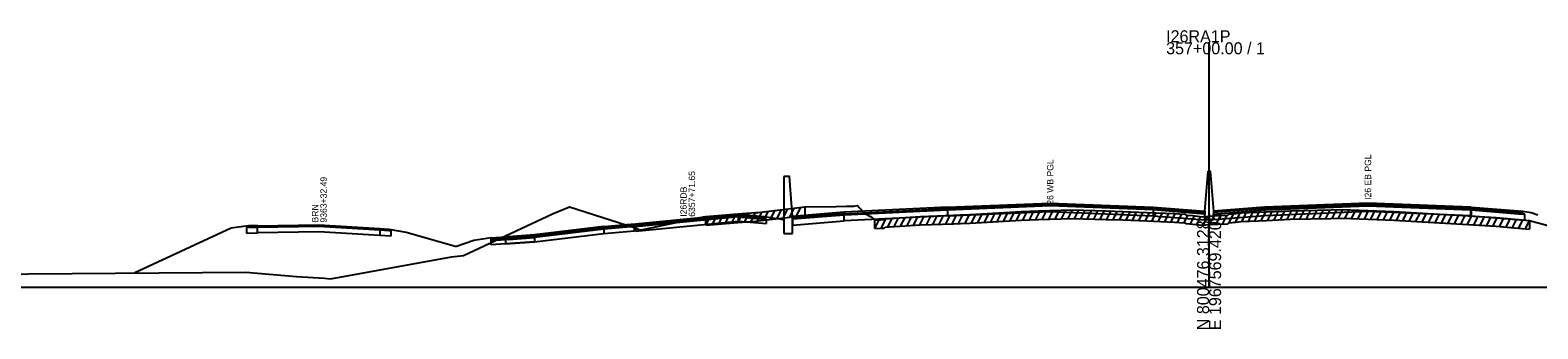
# Model space of a CAD drawing. Extents: x 1017 to 19997, y -1947 to 50737.
# Drawn here: x 14325.4 to 14676.6, y 6990.3 to 7060 of the extents above; entities that cross this region are included whole.
import ezdxf

# ---------------------------------------------------------------- set-up
doc = ezdxf.new("R2010")
doc.units = 0
for name, color, linetype in [('RD_GPK_XS_Cell', 7, 'Continuous'), ('RD_XS_Base', 7, 'Continuous'), ('RD_XS_ExGround', 7, 'Continuous'), ('RD_XS_ExPaveRet', 7, 'Continuous'), ('RD_XS_Greenside', 7, 'Continuous'), ('RD_XS_MedBWall', 7, 'Continuous'), ('RD_XS_Pave', 7, 'Continuous'), ('RD_XS_PaveOvlay', 7, 'Continuous'), ('RD_XS_TX_Notes', 7, 'Continuous')]:
    doc.layers.add(name, color=color, linetype=linetype)

msp = doc.modelspace()

# ---------------------------------------------------------------- linework, layer by layer
at = {"layer": 'RD_GPK_XS_Cell'}
for p, q in [((14600, 7000), (14600, 7057.14)), ((14000, 7000), (14600, 7000)), ((14600, 7000), (15200, 7000))]:
    msp.add_line(p, q, dxfattribs=at)
at = {"layer": 'RD_XS_Base'}
for points in [[(14490.4, 7015.41), (14490.4, 7016.41)], [(14496.9, 7015.88), (14496.4, 7015.92), (14490.4, 7016.41)], [(14496.9, 7014.88), (14496.9, 7015.88)], [(14515, 7016.82), (14503, 7015.86)], [(14503, 7015.86), (14503, 7014.52)], [(14515, 7015.48), (14515, 7016.82)], [(14539.05, 7016.68), (14515, 7015.48)], [(14539.05, 7018.02), (14539.05, 7016.68)], [(14539.05, 7016.68), (14563, 7017.65), (14587, 7016.69)], [(14599, 7017.08), (14587, 7018.03)], [(14587, 7018.03), (14587, 7016.69)], [(14587, 7016.69), (14599, 7015.74)], [(14599, 7015.74), (14599, 7017.08)], [(14601, 7015.74), (14601, 7017.08)], [(14613, 7016.69), (14601, 7015.74)], [(14613, 7016.69), (14613, 7018.03)], [(14660.95, 7016.69), (14637, 7017.65), (14613, 7016.69)], [(14660.95, 7016.69), (14660.95, 7018.03)], [(14661, 7016.69), (14660.95, 7016.69)], [(14661, 7018.03), (14661, 7016.69)], [(14673.5, 7017.03), (14673, 7017.07), (14661, 7018.03)], [(14661, 7016.69), (14673.5, 7015.69)], [(14673.5, 7015.69), (14673.5, 7017.03)], [(14378.35, 7014.02), (14375.8, 7013.98)], [(14375.8, 7013.98), (14375.8, 7012.65)], [(14375.8, 7012.65), (14378.35, 7012.69)], [(14378.35, 7014.02), (14392.63, 7014.26), (14406.9, 7013.39)], [(14378.35, 7012.69), (14378.35, 7014.02)], [(14406.9, 7012.08), (14392.63, 7012.93), (14378.35, 7012.69)], [(14406.9, 7013.39), (14406.9, 7012.08)], [(14406.9, 7013.39), (14408.94, 7013.27), (14409.45, 7013.24)], [(14409.45, 7011.9), (14406.9, 7012.08)], [(14409.45, 7013.24), (14409.45, 7011.9)], [(14442.9, 7010.6), (14459.08, 7012.56)], [(14466.17, 7014.17), (14459.08, 7013.56)], [(14459.08, 7013.56), (14459.08, 7012.56)], [(14459.08, 7012.56), (14466.17, 7013.17)], [(14466.17, 7013.17), (14466.17, 7014.17)], [(14466.4, 7013.11), (14478.4, 7014.26), (14490.4, 7015.41)], [(14466.4, 7014.11), (14466.4, 7013.11)], [(14490.4, 7015.41), (14496.9, 7014.88)], [(14503, 7014.52), (14515, 7015.48)], [(14432.79, 7010.9), (14442.9, 7011.6)], [(14432.79, 7009.9), (14432.79, 7010.9)], [(14442.9, 7010.6), (14432.79, 7009.9)], [(14442.9, 7011.6), (14436.84, 7011.18), (14436.13, 7011.13)], [(14436.13, 7011.13), (14436.13, 7010.13)], [(14436.13, 7010.13), (14442.9, 7010.6)], [(14442.9, 7011.6), (14442.9, 7010.6)]]:
    msp.add_lwpolyline(points, dxfattribs=at)
at = {"layer": 'RD_XS_ExGround'}
msp.add_lwpolyline([(14314.9, 7003.09), (14375.7, 7003.54), (14387.45, 7002.53), (14393.97, 7002.1), (14395.27, 7002.01), (14397.59, 7002.39), (14423.56, 7007.1), (14426.37, 7007.42), (14447.06, 7017.15), (14451.01, 7018.79), (14466.33, 7013.86), (14467.41, 7013.37), (14468.14, 7013.51), (14482.23, 7016.43), (14482.83, 7016.53), (14490.26, 7017.11), (14494.41, 7017.43), (14494.96, 7017.48), (14495.64, 7017.56), (14505.85, 7018.73), (14513.19, 7018.84), (14515.51, 7018.92), (14517.24, 7018.94), (14518.12, 7019.05), (14518.53, 7018.65), (14519.74, 7017.32), (14520.17, 7017.03), (14521.13, 7016.51), (14522.16, 7015.71), (14523.47, 7015.76), (14524.34, 7015.82), (14524.6, 7016.02), (14525.57, 7016.08), (14532.83, 7016.55), (14540.45, 7016.82), (14542.11, 7016.88), (14544.31, 7016.95), (14545.68, 7017.03), (14556.22, 7017.67), (14560.31, 7017.8), (14568.2, 7018.06), (14575.99, 7017.83), (14579.9, 7017.71), (14585.48, 7017.47), (14591.92, 7017.21), (14593.13, 7017.13), (14594.37, 7017.02), (14594.7, 7016.86), (14596.22, 7016.72), (14598.39, 7016.46), (14600.12, 7016.62), (14601.02, 7016.69), (14602.13, 7016.73), (14604.37, 7016.79), (14604.63, 7017.03), (14606.23, 7017.21), (14607.45, 7017.36), (14613.4, 7017.62), (14618.97, 7017.87), (14628.39, 7018.06), (14631.11, 7018.13), (14634.94, 7017.97), (14643.14, 7017.68), (14653.64, 7017.06), (14655.09, 7016.98), (14666.83, 7016.28), (14668.54, 7016.12), (14674.62, 7015.56), (14687.54, 7012.1)], dxfattribs=at)
at = {"layer": 'RD_XS_ExPaveRet'}
for p, q in [((14482.83, 7014.53), (14483.87, 7016.61)), ((14482.83, 7014.53), (14482.83, 7016.53)), ((14484.33, 7014.65), (14485.37, 7016.73)), ((14485.83, 7014.77), (14486.87, 7016.85)), ((14487.33, 7014.88), (14488.37, 7016.96)), ((14488.83, 7015), (14489.87, 7017.08)), ((14490.33, 7015.11), (14491.37, 7017.19)), ((14491.83, 7015.23), (14492.87, 7017.31)), ((14493.33, 7015.35), (14494.37, 7017.43)), ((14494.83, 7015.47), (14495.89, 7017.59)), ((14495.64, 7015.56), (14505.85, 7016.73)), ((14496.33, 7015.64), (14497.39, 7017.76)), ((14497.83, 7015.81), (14498.89, 7017.93)), ((14499.33, 7015.98), (14500.39, 7018.1)), ((14500.83, 7016.15), (14501.89, 7018.28)), ((14502.33, 7016.33), (14503.39, 7018.45)), ((14503.83, 7016.5), (14504.89, 7018.62)), ((14505.85, 7018.73), (14505.85, 7016.73)), ((14522.16, 7013.71), (14523.17, 7015.75)), ((14522.16, 7013.71), (14522.16, 7015.71)), ((14523.66, 7013.77), (14524.79, 7016.03)), ((14525.16, 7014.06), (14526.19, 7016.12)), ((14526.66, 7014.15), (14527.69, 7016.22)), ((14528.16, 7014.25), (14529.19, 7016.31)), ((14529.66, 7014.34), (14530.69, 7016.41)), ((14531.16, 7014.44), (14532.19, 7016.51)), ((14532.66, 7014.54), (14533.68, 7016.58)), ((14534.16, 7014.59), (14535.17, 7016.63)), ((14535.66, 7014.65), (14536.67, 7016.68)), ((14537.16, 7014.7), (14538.17, 7016.74)), ((14538.66, 7014.76), (14539.67, 7016.79)), ((14540.16, 7014.81), (14541.17, 7016.84)), ((14541.66, 7014.86), (14542.67, 7016.9)), ((14543.16, 7014.91), (14544.17, 7016.95)), ((14544.66, 7014.97), (14545.69, 7017.03)), ((14545.68, 7015.03), (14556.22, 7015.67)), ((14546.16, 7015.06), (14547.19, 7017.12)), ((14547.66, 7015.15), (14548.69, 7017.21)), ((14549.16, 7015.24), (14550.19, 7017.3)), ((14550.66, 7015.33), (14551.69, 7017.39)), ((14552.16, 7015.42), (14553.19, 7017.49)), ((14553.66, 7015.51), (14554.69, 7017.58)), ((14555.16, 7015.6), (14556.19, 7017.67)), ((14556.22, 7015.67), (14560.31, 7015.8)), ((14556.66, 7015.68), (14557.67, 7017.71)), ((14558.16, 7015.73), (14559.17, 7017.76)), ((14559.66, 7015.78), (14560.67, 7017.81)), ((14560.31, 7015.8), (14568.2, 7016.06)), ((14561.16, 7015.83), (14562.17, 7017.86)), ((14562.66, 7015.88), (14563.67, 7017.91)), ((14564.16, 7015.93), (14565.17, 7017.96)), ((14565.66, 7015.98), (14566.67, 7018.01)), ((14567.16, 7016.03), (14568.17, 7018.06)), ((14568.2, 7016.06), (14575.99, 7015.83)), ((14568.66, 7016.05), (14569.64, 7018.02)), ((14570.16, 7016), (14571.14, 7017.97)), ((14571.66, 7015.96), (14572.64, 7017.93)), ((14573.16, 7015.91), (14574.14, 7017.88)), ((14574.66, 7015.87), (14575.64, 7017.84)), ((14575.99, 7015.83), (14579.9, 7015.71)), ((14576.16, 7015.82), (14577.14, 7017.79)), ((14577.66, 7015.78), (14578.64, 7017.75)), ((14579.16, 7015.73), (14580.14, 7017.7)), ((14579.9, 7015.71), (14585.48, 7015.47)), ((14580.66, 7015.68), (14581.63, 7017.64)), ((14582.16, 7015.61), (14583.13, 7017.57)), ((14583.66, 7015.55), (14584.63, 7017.51)), ((14585.16, 7015.49), (14586.14, 7017.45)), ((14586.66, 7015.43), (14587.64, 7017.39)), ((14588.16, 7015.37), (14589.14, 7017.33)), ((14589.66, 7015.3), (14590.64, 7017.26)), ((14591.16, 7015.24), (14592.13, 7017.2)), ((14592.66, 7015.16), (14593.62, 7017.09)), ((14594.16, 7015.04), (14595.05, 7016.83)), ((14595.66, 7014.77), (14596.61, 7016.67)), ((14597.16, 7014.61), (14598.1, 7016.49)), ((14598.66, 7014.48), (14599.7, 7016.58)), ((14600.16, 7014.62), (14601.19, 7016.7)), ((14601.66, 7014.71), (14602.67, 7016.74)), ((14603.16, 7014.76), (14604.17, 7016.78)), ((14604.66, 7015.03), (14605.71, 7017.15)), ((14606.16, 7015.2), (14607.22, 7017.33)), ((14607.45, 7015.36), (14613.4, 7015.62)), ((14607.66, 7015.37), (14608.68, 7017.41)), ((14609.16, 7015.43), (14610.18, 7017.48)), ((14610.66, 7015.5), (14611.68, 7017.54)), ((14612.16, 7015.56), (14613.18, 7017.61)), ((14613.4, 7015.62), (14618.97, 7015.87)), ((14613.66, 7015.63), (14614.68, 7017.67)), ((14615.16, 7015.7), (14616.18, 7017.74)), ((14616.66, 7015.76), (14617.68, 7017.81)), ((14618.16, 7015.83), (14619.18, 7017.87)), ((14618.97, 7015.87), (14628.39, 7016.06)), ((14619.66, 7015.88), (14620.67, 7017.9)), ((14621.16, 7015.91), (14622.17, 7017.93)), ((14622.66, 7015.94), (14623.67, 7017.97)), ((14624.16, 7015.98), (14625.17, 7018)), ((14625.66, 7016.01), (14626.67, 7018.03)), ((14627.16, 7016.04), (14628.17, 7018.06)), ((14628.39, 7016.06), (14631.11, 7016.13)), ((14628.66, 7016.07), (14629.67, 7018.09)), ((14630.16, 7016.1), (14631.17, 7018.12)), ((14631.11, 7016.13), (14634.94, 7015.97)), ((14631.66, 7016.1), (14632.64, 7018.06)), ((14633.16, 7016.04), (14634.14, 7018)), ((14634.66, 7015.98), (14635.64, 7017.95)), ((14634.94, 7015.97), (14643.14, 7015.68)), ((14636.16, 7015.93), (14637.14, 7017.89)), ((14637.66, 7015.87), (14638.64, 7017.84)), ((14639.16, 7015.82), (14640.14, 7017.79)), ((14640.66, 7015.77), (14641.64, 7017.73)), ((14642.16, 7015.72), (14643.14, 7017.68)), ((14643.14, 7015.68), (14653.64, 7015.06)), ((14643.66, 7015.65), (14644.63, 7017.59)), ((14645.16, 7015.56), (14646.13, 7017.51)), ((14646.66, 7015.47), (14647.63, 7017.42)), ((14648.16, 7015.39), (14649.13, 7017.33)), ((14649.66, 7015.3), (14650.63, 7017.24)), ((14651.16, 7015.21), (14652.13, 7017.15)), ((14652.66, 7015.12), (14653.63, 7017.06)), ((14654.16, 7015.03), (14655.13, 7016.97)), ((14655.66, 7014.94), (14656.63, 7016.89)), ((14657.16, 7014.85), (14658.13, 7016.8)), ((14658.66, 7014.76), (14659.63, 7016.71)), ((14660.16, 7014.68), (14661.13, 7016.62)), ((14661.66, 7014.59), (14662.63, 7016.53)), ((14663.16, 7014.5), (14664.13, 7016.44)), ((14664.66, 7014.41), (14665.63, 7016.35)), ((14666.16, 7014.32), (14667.12, 7016.25)), ((14667.66, 7014.2), (14668.61, 7016.11)), ((14669.16, 7014.06), (14670.11, 7015.98)), ((14670.66, 7013.93), (14671.61, 7015.84)), ((14672.16, 7013.79), (14673.11, 7015.7)), ((14482.83, 7014.53), (14490.26, 7015.11)), ((14490.26, 7015.11), (14494.41, 7015.43)), ((14494.41, 7015.43), (14494.96, 7015.48)), ((14494.96, 7015.48), (14495.64, 7015.56)), ((14522.16, 7013.71), (14523.47, 7013.76)), ((14523.47, 7013.76), (14524.34, 7013.82)), ((14524.34, 7013.82), (14524.6, 7014.02)), ((14524.6, 7014.02), (14525.57, 7014.08)), ((14525.57, 7014.08), (14532.83, 7014.55)), ((14532.83, 7014.55), (14540.45, 7014.82)), ((14540.45, 7014.82), (14542.11, 7014.88)), ((14542.11, 7014.88), (14544.31, 7014.95)), ((14544.31, 7014.95), (14545.68, 7015.03)), ((14585.48, 7015.47), (14591.92, 7015.21)), ((14591.92, 7015.21), (14593.13, 7015.13)), ((14593.13, 7015.13), (14594.37, 7015.02)), ((14594.37, 7015.02), (14594.7, 7014.86)), ((14594.7, 7014.86), (14596.22, 7014.72)), ((14596.22, 7014.72), (14598.39, 7014.46)), ((14598.39, 7014.46), (14600.12, 7014.62)), ((14600.12, 7014.62), (14601.02, 7014.69)), ((14601.02, 7014.69), (14602.13, 7014.73)), ((14602.13, 7014.73), (14604.37, 7014.79)), ((14604.37, 7014.79), (14604.63, 7015.03)), ((14604.63, 7015.03), (14606.23, 7015.21)), ((14606.23, 7015.21), (14607.45, 7015.36)), ((14653.64, 7015.06), (14655.09, 7014.98)), ((14655.09, 7014.98), (14666.83, 7014.28)), ((14666.83, 7014.28), (14668.54, 7014.12)), ((14668.54, 7014.12), (14674.62, 7013.56)), ((14673.66, 7013.65), (14674.61, 7015.56)), ((14674.62, 7015.56), (14674.62, 7013.56))]:
    msp.add_line(p, q, dxfattribs=at)
at = {"layer": 'RD_XS_Greenside'}
for points in [[(14496.4, 7016.55), (14500.4, 7015.91)], [(14500.4, 7015.91), (14501, 7015.71)], [(14673, 7017.74), (14675, 7017.41)], [(14675, 7017.41), (14676.57, 7016.88)], [(14372.23, 7013.76), (14349.82, 7003.37)], [(14376.31, 7014.31), (14372.23, 7013.76)], [(14408.94, 7013.58), (14413.02, 7012.86)], [(14413.02, 7012.86), (14424.76, 7009.55)], [(14428.75, 7010.93), (14424.76, 7009.55)], [(14432.79, 7011.53), (14428.75, 7010.93)]]:
    msp.add_lwpolyline(points, dxfattribs=at)
at = {"layer": 'RD_XS_MedBWall'}
for points in [[(14599, 7017.74), (14599.75, 7027.08)], [(14599.75, 7027.08), (14600.25, 7027.08), (14601, 7017.74)], [(14503, 7016.54), (14502.25, 7025.88), (14501, 7025.88)], [(14501, 7025.88), (14501, 7012.54)], [(14503, 7012.54), (14503, 7016.54)], [(14599, 7015.74), (14599, 7017.08), (14599, 7017.74)], [(14601, 7015.74), (14599, 7015.74)], [(14601, 7017.74), (14601, 7017.08), (14601, 7015.74)], [(14501, 7012.54), (14503, 7012.54)]]:
    msp.add_lwpolyline(points, dxfattribs=at)
at = {"layer": 'RD_XS_Pave'}
for points in [[(14660.95, 7018.37), (14637, 7019.33), (14613, 7018.37)], [(14466.4, 7014.43), (14478.4, 7015.58), (14490.4, 7016.73)], [(14490.4, 7016.41), (14478.4, 7015.26), (14466.4, 7014.11)], [(14490.4, 7016.73), (14490.4, 7016.41)], [(14496.4, 7016.24), (14490.4, 7016.73)], [(14490.4, 7016.41), (14496.4, 7015.92)], [(14496.4, 7015.92), (14496.4, 7016.24)], [(14515, 7017.16), (14503, 7016.2)], [(14503, 7016.2), (14503, 7015.86)], [(14515, 7017.16), (14539.05, 7018.36)], [(14539.05, 7018.02), (14515, 7016.82)], [(14515, 7016.82), (14515, 7017.16)], [(14587, 7018.03), (14563, 7018.99), (14539.05, 7018.02)], [(14539.05, 7018.36), (14539.05, 7018.02)], [(14587, 7018.37), (14587, 7018.03)], [(14587, 7018.37), (14599, 7017.42)], [(14599, 7017.42), (14599, 7017.08)], [(14613, 7018.37), (14601, 7017.42)], [(14601, 7017.08), (14613, 7018.03)], [(14601, 7017.42), (14601, 7017.08)], [(14613, 7018.03), (14637, 7018.99), (14660.95, 7018.03)], [(14613, 7018.03), (14613, 7018.37)], [(14660.95, 7018.37), (14661, 7018.37)], [(14660.95, 7018.03), (14660.95, 7018.37)], [(14661, 7018.03), (14660.95, 7018.03)], [(14661, 7018.37), (14661, 7018.03)], [(14661, 7018.03), (14673, 7017.07)], [(14673, 7017.07), (14673, 7017.41)], [(14442.9, 7011.92), (14459.08, 7013.87)], [(14459.08, 7013.56), (14442.9, 7011.6)], [(14459.08, 7013.87), (14466.17, 7014.49)], [(14459.08, 7013.87), (14459.08, 7013.56)], [(14466.17, 7014.49), (14466.17, 7014.17)], [(14466.4, 7014.11), (14466.4, 7014.43)], [(14432.79, 7010.9), (14432.79, 7011.22)], [(14442.9, 7011.92), (14436.84, 7011.5)], [(14436.84, 7011.18), (14442.9, 7011.6)], [(14436.84, 7011.5), (14436.84, 7011.18)], [(14442.9, 7011.6), (14442.9, 7011.92)]]:
    msp.add_lwpolyline(points, dxfattribs=at)
at = {"layer": 'RD_XS_PaveOvlay'}
for points in [[(14539.05, 7018.7), (14563, 7019.66), (14587, 7018.7)], [(14587, 7018.37), (14563, 7019.33), (14539.05, 7018.36)], [(14660.95, 7018.7), (14637, 7019.66), (14613, 7018.7)], [(14490.4, 7017.05), (14478.4, 7015.9), (14466.4, 7014.75)], [(14490.4, 7016.73), (14490.4, 7017.05)], [(14490.4, 7017.05), (14496.4, 7016.55)], [(14496.4, 7016.55), (14496.4, 7016.24)], [(14515, 7017.5), (14503, 7016.54)], [(14503, 7016.54), (14503, 7016.2)], [(14539.05, 7018.7), (14515, 7017.5)], [(14515, 7017.5), (14515, 7017.16)], [(14539.05, 7018.36), (14539.05, 7018.7)], [(14587, 7018.7), (14587, 7018.37)], [(14587, 7018.7), (14599, 7017.74)], [(14599, 7017.74), (14599, 7017.42)], [(14613, 7018.7), (14601, 7017.74)], [(14601, 7017.74), (14601, 7017.42)], [(14613, 7018.37), (14613, 7018.7)], [(14660.95, 7018.7), (14661, 7018.7)], [(14660.95, 7018.37), (14660.95, 7018.7)], [(14661, 7018.7), (14673, 7017.74)], [(14661, 7018.37), (14661, 7018.7)], [(14673, 7017.41), (14661, 7018.37)], [(14673, 7017.74), (14673, 7017.41)], [(14378.35, 7014.34), (14376.31, 7014.31)], [(14376.31, 7014.31), (14376.31, 7013.99)], [(14376.31, 7013.99), (14378.35, 7014.02)], [(14378.35, 7014.34), (14392.63, 7014.58), (14406.9, 7013.71)], [(14378.35, 7014.02), (14378.35, 7014.34)], [(14406.9, 7013.71), (14406.9, 7013.39)], [(14406.9, 7013.71), (14408.94, 7013.58)], [(14408.94, 7013.27), (14406.9, 7013.39)], [(14408.94, 7013.58), (14408.94, 7013.27)], [(14432.79, 7011.53), (14442.9, 7012.23)], [(14442.9, 7012.23), (14436.84, 7011.81)], [(14459.08, 7014.19), (14442.9, 7012.23)], [(14442.9, 7012.23), (14442.9, 7011.92)], [(14459.08, 7014.19), (14466.17, 7014.81)], [(14459.08, 7013.87), (14459.08, 7014.19)], [(14466.17, 7014.81), (14466.17, 7014.49)], [(14466.4, 7014.75), (14466.4, 7014.43)], [(14442.9, 7011.92), (14432.79, 7011.22)], [(14432.79, 7011.22), (14432.79, 7011.53)], [(14436.84, 7011.81), (14436.84, 7011.5)]]:
    msp.add_lwpolyline(points, dxfattribs=at)

# ---------------------------------------------------------------- texts
at = {"layer": 'RD_GPK_XS_Cell'}
for s, p in [('I26RA1P', (14590, 7057.14)), ('357+00.00 / 1', (14590, 7054.34))]:
    msp.add_text(s, height=2.8, dxfattribs=at).set_placement(p)
for s, p in [('E 1967569.4205', (14602.8, 6990)), ('N 800476.3128', (14600, 6990))]:
    msp.add_text(s, height=2.8, rotation=90, dxfattribs=at).set_placement(p)
at = {"layer": 'RD_XS_TX_Notes'}
for s, p in [('I26 WB PGL', (14563.75, 7018.7)), ('I26 EB PGL', (14637.75, 7020.39)), (' 6357+71.65', (14480.3, 7015.9)), (' 9363+32.49', (14394.51, 7014.55)), (' I26RDB', (14478.35, 7015.9)), (' BRN', (14392.55, 7014.55))]:
    msp.add_text(s, height=1.5, rotation=90, dxfattribs=at).set_placement(p)

doc.saveas('drawing.dxf')
